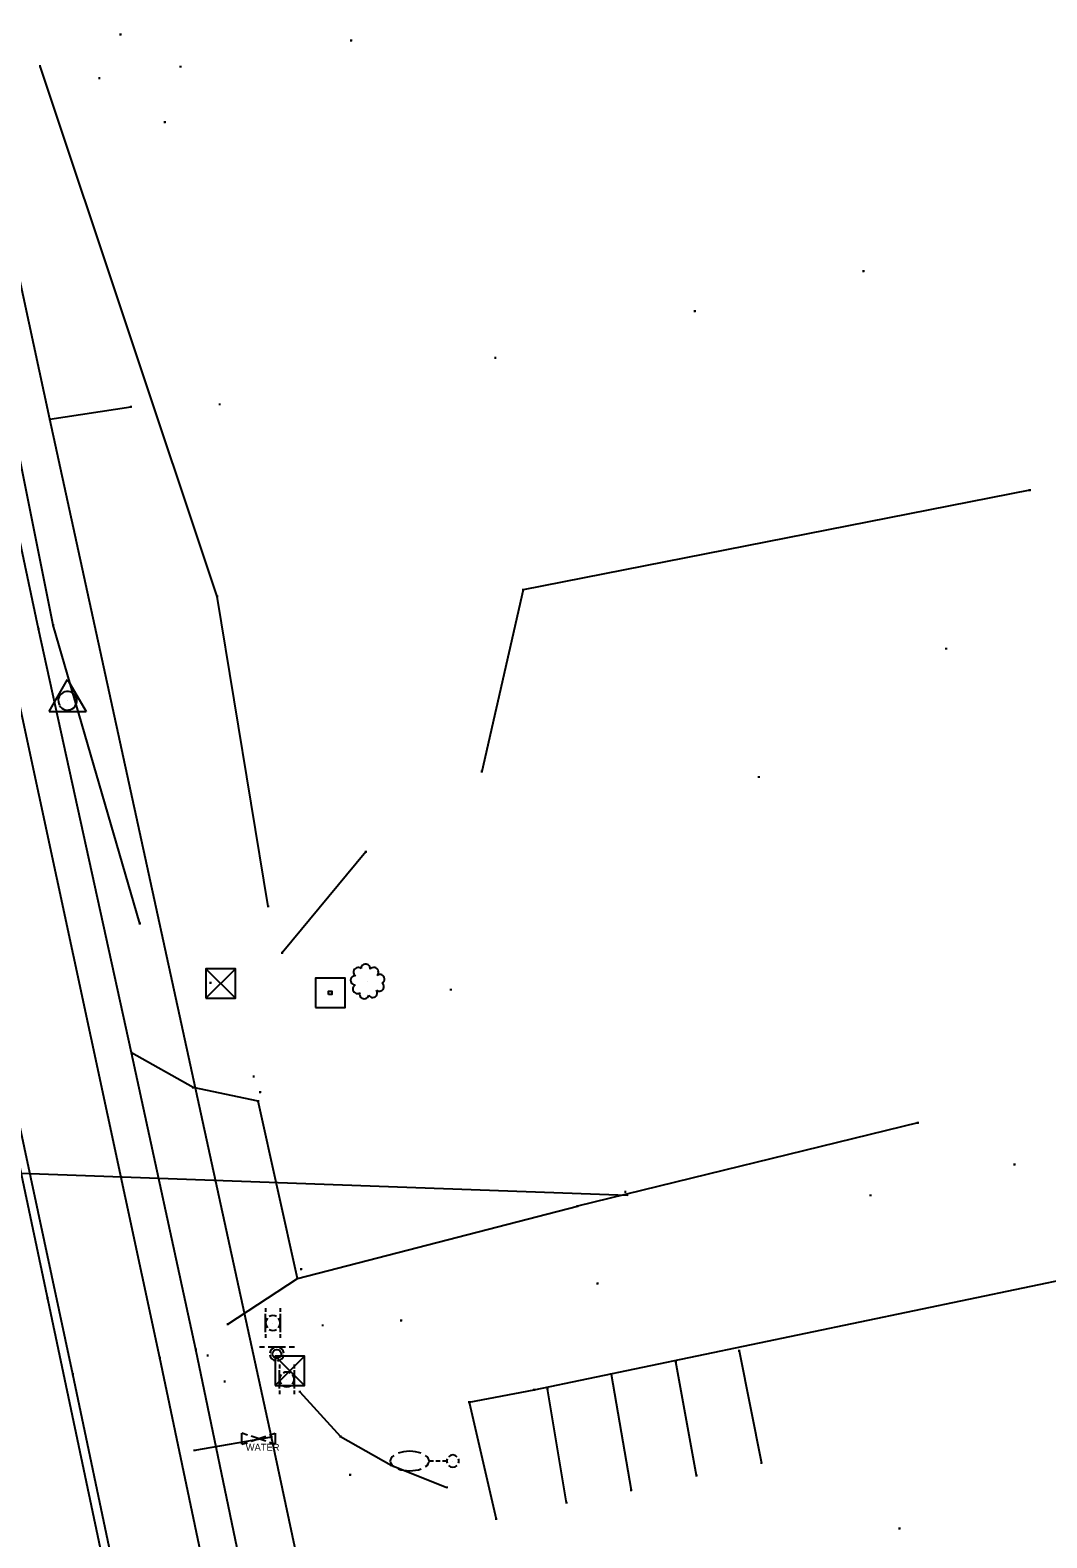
# Model space of a CAD drawing. Extents: x 1954856 to 2011933, y 399149 to 426294.
# Drawn here: x 2005902.3 to 2006040.2, y 403651.8 to 403856.4 of the extents above; entities that cross this region are included whole.
import ezdxf

# ---------------------------------------------------------------- set-up
doc = ezdxf.new("R2010")
doc.units = 0
for name, color, linetype in [('BankMent_ep', 7, 'Continuous'), ('BaselineSurvey', 7, 'Continuous'), ('DelineatorPost_ep', 7, 'Continuous'), ('Driveway_ep', 7, 'Continuous'), ('ElecAer_ep', 7, 'Continuous'), ('Fence_ep', 7, 'Continuous'), ('GroundShot_ep', 7, 'Continuous'), ('Luminaire_ep', 7, 'Continuous'), ('MonumentCC_ep', 7, 'Continuous'), ('MonumentIRC_ep', 7, 'Continuous'), ('MonumentPST_ep', 7, 'Continuous'), ('PavtAsphalt_ep', 7, 'Continuous'), ('PavtAsphaltCrown_ep', 7, 'Continuous'), ('PavtMisc_ep', 7, 'Continuous'), ('PMRK_ep', 7, 'Continuous'), ('PointLocator_ep', 7, 'Continuous'), ('ShldrPaved_ep', 7, 'Continuous'), ('SignSingle_ep', 7, 'Continuous'), ('TreeOak_ep', 7, 'Continuous'), ('ValveWater_ep', 7, 'Continuous'), ('WaterB_ep', 7, 'Continuous')]:
    doc.layers.add(name, color=color, linetype=linetype)

msp = doc.modelspace()

# ---------------------------------------------------------------- linework, layer by layer
at = {"layer": 'BankMent_ep'}
for p, q in [((2005927.68, 403779.55), (2005903.63, 403851.51)), ((2005905.4, 403775.65), (2005893.76, 403833.79)), ((2005917.19, 403735.17), (2005905.4, 403775.65)), ((2005947.84, 403744.92), (2005936.49, 403731.21))]:
    msp.add_line(p, q, dxfattribs=at)
msp.add_lwpolyline([(2005934.6, 403737.51), (2005927.68, 403779.55)], dxfattribs=at)
at = {"layer": 'BaselineSurvey'}
msp.add_line((2006223.92, 402174.38), (2005094.48, 407516.05), dxfattribs=at)
msp.add_line((2006223.92, 402174.38), (2005094.48, 407516.05), dxfattribs=at)
at = {"layer": 'DelineatorPost_ep'}
for p, q in [((2005934.23, 403682.97), (2005934.23, 403682.47)), ((2005934.23, 403679.72), (2005934.23, 403682.22)), ((2005936.23, 403682.97), (2005936.23, 403682.47)), ((2005936.23, 403682.22), (2005936.23, 403679.72)), ((2005934.23, 403679.47), (2005934.23, 403678.97)), ((2005935.23, 403680.97), (2005935.23, 403680.97)), ((2005936.23, 403679.47), (2005936.23, 403678.97)), ((2005936.12, 403675.32), (2005936.12, 403674.82)), ((2005938.12, 403675.32), (2005938.12, 403674.82)), ((2005936.12, 403672.07), (2005936.12, 403674.57)), ((2005937.12, 403673.32), (2005937.12, 403673.32)), ((2005938.12, 403674.57), (2005938.12, 403672.07)), ((2005936.12, 403671.82), (2005936.12, 403671.32)), ((2005938.12, 403671.82), (2005938.12, 403671.32))]:
    msp.add_line(p, q, dxfattribs=at)
for centre, start, end in [((2005935.23, 403680.97), 138.5904, 221.4096), ((2005935.23, 403680.97), 60, 120), ((2005935.23, 403680.97), 318.5904, 41.4096), ((2005935.23, 403680.97), 240, 300), ((2005937.12, 403673.32), 138.5904, 221.4096), ((2005937.12, 403673.32), 60, 120), ((2005937.12, 403673.32), 318.5904, 41.4096), ((2005937.12, 403673.32), 240, 300)]:
    msp.add_arc(centre, 1, start, end, dxfattribs=at)
at = {"layer": 'Driveway_ep'}
for p, q in [((2006037.93, 403793.98), (2005969.18, 403780.48)), ((2005969.18, 403780.48), (2005963.57, 403755.79)), ((2005924.4, 403712.93), (2005916.05, 403717.64)), ((2005933.24, 403711.08), (2005924.4, 403712.93)), ((2005938.57, 403687.03), (2005933.24, 403711.08)), ((2005929.13, 403680.81), (2005938.57, 403687.03)), ((2005961.87, 403670.23), (2005965.52, 403654.36))]:
    msp.add_line(p, q, dxfattribs=at)
for points in [[(2006037.93, 403793.98), (2005969.18, 403780.48), (2005963.57, 403755.79)], [(2006022.73, 403708.13), (2005976.55, 403696.84)], [(2005938.57, 403687.03), (2005976.55, 403696.84)]]:
    msp.add_lwpolyline(points, dxfattribs=at)
at = {"layer": 'ElecAer_ep'}
msp.add_lwpolyline([(2005962.93, 403244.33), (2005923.16, 403436.14), (2005867.36, 403702.52), (2005983.3, 403698.34)], dxfattribs=at)
at = {"layer": 'Fence_ep'}
msp.add_lwpolyline([(2005938.88, 403671.64), (2005944.41, 403665.56), (2005951.26, 403661.68), (2005958.83, 403658.67)], dxfattribs=at)
at = {"layer": 'GroundShot_ep'}
for p, q in [((2006015.49, 403823.71), (2006015.24, 403823.71)), ((2006015.36, 403823.58), (2006015.36, 403823.83)), ((2006015.36, 403823.71), (2006015.36, 403823.71)), ((2006026.71, 403772.47), (2006026.46, 403772.47)), ((2006026.58, 403772.35), (2006026.58, 403772.6)), ((2006026.58, 403772.47), (2006026.58, 403772.47)), ((2006035.98, 403702.49), (2006035.73, 403702.49)), ((2006035.85, 403702.36), (2006035.85, 403702.61)), ((2006035.85, 403702.49), (2006035.85, 403702.49))]:
    msp.add_line(p, q, dxfattribs=at)
at = {"layer": 'Luminaire_ep'}
for p, q in [((2005957.02, 403662.24), (2005956.42, 403662.24)), ((2005957.92, 403662.24), (2005957.32, 403662.24)), ((2005958.82, 403662.24), (2005958.22, 403662.24)), ((2005959.65, 403662.24), (2005959.65, 403662.24))]:
    msp.add_line(p, q, dxfattribs=at)
for start, end in [(45, 135), (159.9115, 200.0885), (225, 315), (339.9115, 20.0885)]:
    msp.add_arc((2005959.65, 403662.24), 0.825, start, end, dxfattribs=at)
for start_param, end_param in [(5.668326, 6.898045), (4.075781, 5.348997), (2.526733, 3.756452), (0.934187, 2.207405)]:
    msp.add_ellipse((2005953.78, 403662.24), major_axis=(-2.64, 0), ratio=0.5, start_param=start_param, end_param=end_param, dxfattribs=at)
at = {"layer": 'MonumentCC_ep'}
msp.add_line((2005943.01, 403725.78), (2005943.01, 403725.78), dxfattribs=at)
msp.add_lwpolyline([(2005941.01, 403723.78), (2005945.01, 403723.78), (2005945.01, 403727.78), (2005941.01, 403727.78), (2005941.01, 403723.78)], dxfattribs=at)
msp.add_lwpolyline([(2005942.77, 403725.55), (2005942.77, 403726.02), (2005943.24, 403726.02), (2005943.24, 403725.55)], close=True, dxfattribs=at)
at = {"layer": 'MonumentIRC_ep'}
for p, q in [((2005904.87, 403763.96), (2005907.37, 403768.29)), ((2005907.37, 403768.29), (2005909.87, 403763.96)), ((2005907.37, 403765.41), (2005907.37, 403765.41)), ((2005904.87, 403763.96), (2005909.87, 403763.96))]:
    msp.add_line(p, q, dxfattribs=at)
msp.add_arc((2005907.37, 403765.41), 1.26, 209.9294, 209.03, dxfattribs=at)
at = {"layer": 'MonumentPST_ep'}
for p, q in [((2005926.14, 403729.03), (2005930.14, 403725.03)), ((2005926.14, 403725.03), (2005930.14, 403729.03)), ((2005928.14, 403727.03), (2005928.14, 403727.03)), ((2005935.52, 403676.48), (2005939.52, 403672.48)), ((2005935.52, 403672.48), (2005939.52, 403676.48)), ((2005937.52, 403674.48), (2005937.52, 403674.48))]:
    msp.add_line(p, q, dxfattribs=at)
for points in [[(2005926.14, 403725.03), (2005930.14, 403725.03), (2005930.14, 403729.03), (2005926.14, 403729.03), (2005926.14, 403725.03)], [(2005935.52, 403672.48), (2005939.52, 403672.48), (2005939.52, 403676.48), (2005935.52, 403676.48), (2005935.52, 403672.48)]]:
    msp.add_lwpolyline(points, dxfattribs=at)
at = {"layer": 'PavtAsphalt_ep'}
msp.add_lwpolyline([(2006233.39, 402199.4), (2006231.31, 402208.78), (2006210.3, 402306.91), (2006189.73, 402404.41), (2006168.52, 402502.44), (2006147.45, 402600.55), (2006127, 402698.2), (2006106.48, 402795.48), (2006085.7, 402893.48), (2006064.78, 402991.32), (2006043.91, 403089.28), (2006023.05, 403187.5), (2006002.57, 403285.23), (2005981.7, 403382.7), (2005961.21, 403480.5), (2005940.45, 403578.3), (2005919.87, 403676.23), (2005898.84, 403774.26)], dxfattribs=at)
at = {"layer": 'PavtAsphaltCrown_ep'}
msp.add_lwpolyline([(2006221.58, 402197.04), (2006219.37, 402206.69), (2006198.42, 402304.43), (2006177.67, 402402.21), (2006156.49, 402500.14), (2006135.92, 402597.88), (2006115.39, 402695.49), (2006094.3, 402793.44), (2006073.8, 402891.43), (2006052.86, 402989.16), (2006032.08, 403086.96), (2006011.06, 403184.66), (2005990.58, 403282.63), (2005969.86, 403380.23), (2005949.3, 403478.33), (2005928.68, 403576.1), (2005908.1, 403674.03), (2005887.14, 403771.84)], dxfattribs=at)
at = {"layer": 'PavtMisc_ep'}
for points in [[(2005961.87, 403670.23), (2005970.68, 403671.89), (2006044.38, 403687.3), (2006113.91, 403701.04)], [(2005970.68, 403671.89), (2006044.38, 403687.3), (2006113.91, 403701.04)]]:
    msp.add_lwpolyline(points, dxfattribs=at)
at = {"layer": 'PMRK_ep'}
for points in [[(2005998.51, 403677.19), (2006001.5, 403661.97)], [(2005992.71, 403660.27), (2005989.91, 403675.69)], [(2005981.12, 403674.04), (2005983.83, 403658.27)], [(2005975.08, 403656.59), (2005972.5, 403672.03)]]:
    msp.add_lwpolyline(points, dxfattribs=at)
at = {"layer": 'PointLocator_ep'}
for p, q in [((2005914.67, 403855.81), (2005914.42, 403855.81)), ((2005914.54, 403855.69), (2005914.54, 403855.94)), ((2005914.54, 403855.81), (2005914.54, 403855.81)), ((2005945.96, 403854.99), (2005945.71, 403854.99)), ((2005945.83, 403854.86), (2005945.83, 403855.11)), ((2005945.83, 403854.99), (2005945.83, 403854.99)), ((2005903.75, 403851.51), (2005903.5, 403851.51)), ((2005903.63, 403851.38), (2005903.63, 403851.63)), ((2005903.63, 403851.51), (2005903.63, 403851.51)), ((2005922.82, 403851.45), (2005922.57, 403851.45)), ((2005922.69, 403851.33), (2005922.69, 403851.58)), ((2005922.69, 403851.45), (2005922.69, 403851.45)), ((2005911.8, 403849.9), (2005911.55, 403849.9)), ((2005911.68, 403849.77), (2005911.68, 403850.02)), ((2005911.68, 403849.9), (2005911.68, 403849.9)), ((2005920.7, 403843.91), (2005920.45, 403843.91)), ((2005920.58, 403843.78), (2005920.58, 403844.03)), ((2005920.58, 403843.91), (2005920.58, 403843.91)), ((2005992.49, 403818.13), (2005992.49, 403818.38)), ((2005992.61, 403818.26), (2005992.36, 403818.26)), ((2005992.49, 403818.26), (2005992.49, 403818.26)), ((2005965.53, 403811.92), (2005965.28, 403811.92)), ((2005965.41, 403811.79), (2005965.41, 403812.04)), ((2005965.41, 403811.92), (2005965.41, 403811.92)), ((2005916.09, 403805.27), (2005915.84, 403805.27)), ((2005915.96, 403805.15), (2005915.96, 403805.4)), ((2005915.96, 403805.27), (2005915.96, 403805.27)), ((2005928.14, 403805.63), (2005927.89, 403805.63)), ((2005928.01, 403805.5), (2005928.01, 403805.75)), ((2005928.01, 403805.63), (2005928.01, 403805.63)), ((2005905.1, 403803.61), (2005904.85, 403803.61)), ((2005904.97, 403803.49), (2005904.97, 403803.74)), ((2005904.97, 403803.61), (2005904.97, 403803.61)), ((2006038.06, 403793.98), (2006037.81, 403793.98)), ((2006037.93, 403793.86), (2006037.93, 403794.11)), ((2006037.93, 403793.98), (2006037.93, 403793.98)), ((2005927.8, 403779.55), (2005927.55, 403779.55)), ((2005927.68, 403779.43), (2005927.68, 403779.68)), ((2005927.68, 403779.55), (2005927.68, 403779.55)), ((2005969.31, 403780.48), (2005969.06, 403780.48)), ((2005969.18, 403780.36), (2005969.18, 403780.61)), ((2005969.18, 403780.48), (2005969.18, 403780.48)), ((2005905.53, 403775.65), (2005905.28, 403775.65)), ((2005905.4, 403775.53), (2005905.4, 403775.78)), ((2005905.4, 403775.65), (2005905.4, 403775.65)), ((2005903.54, 403775.17), (2005903.29, 403775.17)), ((2005903.42, 403775.04), (2005903.42, 403775.29)), ((2005903.42, 403775.17), (2005903.42, 403775.17)), ((2005963.7, 403755.79), (2005963.45, 403755.79)), ((2005963.57, 403755.67), (2005963.57, 403755.92)), ((2005963.57, 403755.79), (2005963.57, 403755.79)), ((2006001.28, 403755.05), (2006001.03, 403755.05)), ((2006001.16, 403754.93), (2006001.16, 403755.18)), ((2006001.16, 403755.05), (2006001.16, 403755.05)), ((2005947.97, 403744.92), (2005947.72, 403744.92)), ((2005947.84, 403744.79), (2005947.84, 403745.04)), ((2005947.84, 403744.92), (2005947.84, 403744.92)), ((2005934.72, 403737.51), (2005934.47, 403737.51)), ((2005934.6, 403737.39), (2005934.6, 403737.64)), ((2005934.6, 403737.51), (2005934.6, 403737.51)), ((2005917.31, 403735.17), (2005917.06, 403735.17)), ((2005917.19, 403735.04), (2005917.19, 403735.29)), ((2005917.19, 403735.17), (2005917.19, 403735.17)), ((2005936.61, 403731.21), (2005936.36, 403731.21)), ((2005936.49, 403731.08), (2005936.49, 403731.33)), ((2005936.49, 403731.21), (2005936.49, 403731.21)), ((2005926.88, 403727.12), (2005926.63, 403727.12)), ((2005926.75, 403726.99), (2005926.75, 403727.24)), ((2005926.75, 403727.12), (2005926.75, 403727.12)), ((2005959.36, 403726.07), (2005959.36, 403726.32)), ((2005959.49, 403726.2), (2005959.24, 403726.2)), ((2005959.36, 403726.2), (2005959.36, 403726.2)), ((2005916.18, 403717.64), (2005915.93, 403717.64)), ((2005916.05, 403717.52), (2005916.05, 403717.77)), ((2005916.05, 403717.64), (2005916.05, 403717.64)), ((2005932.75, 403714.42), (2005932.5, 403714.42)), ((2005932.63, 403714.3), (2005932.63, 403714.55)), ((2005932.63, 403714.42), (2005932.63, 403714.42)), ((2005924.53, 403712.93), (2005924.28, 403712.93)), ((2005924.4, 403712.8), (2005924.4, 403713.05)), ((2005924.4, 403712.93), (2005924.4, 403712.93)), ((2005933.62, 403712.29), (2005933.37, 403712.29)), ((2005933.5, 403712.16), (2005933.5, 403712.41)), ((2005933.5, 403712.29), (2005933.5, 403712.29)), ((2005933.37, 403711.08), (2005933.12, 403711.08)), ((2005933.24, 403710.95), (2005933.24, 403711.2)), ((2005933.24, 403711.08), (2005933.24, 403711.08)), ((2006022.85, 403708.13), (2006022.6, 403708.13)), ((2006022.73, 403708.01), (2006022.73, 403708.26)), ((2006022.73, 403708.13), (2006022.73, 403708.13)), ((2005983.17, 403698.77), (2005982.92, 403698.77)), ((2005983.05, 403698.64), (2005983.05, 403698.89)), ((2005983.05, 403698.77), (2005983.05, 403698.77)), ((2005983.43, 403698.34), (2005983.18, 403698.34)), ((2005983.3, 403698.21), (2005983.3, 403698.46)), ((2005983.3, 403698.34), (2005983.3, 403698.34)), ((2006016.43, 403698.29), (2006016.18, 403698.29)), ((2006016.31, 403698.17), (2006016.31, 403698.42)), ((2006016.31, 403698.29), (2006016.31, 403698.29)), ((2005976.68, 403696.84), (2005976.43, 403696.84)), ((2005976.55, 403696.71), (2005976.55, 403696.96)), ((2005976.55, 403696.84), (2005976.55, 403696.84)), ((2005939.2, 403688.27), (2005938.95, 403688.27)), ((2005939.08, 403688.15), (2005939.08, 403688.4)), ((2005939.08, 403688.27), (2005939.08, 403688.27)), ((2005938.69, 403687.03), (2005938.44, 403687.03)), ((2005938.57, 403686.91), (2005938.57, 403687.16)), ((2005938.57, 403687.03), (2005938.57, 403687.03)), ((2005979.42, 403686.31), (2005979.17, 403686.31)), ((2005979.29, 403686.18), (2005979.29, 403686.43)), ((2005979.29, 403686.31), (2005979.29, 403686.31)), ((2005904.78, 403684.34), (2005904.53, 403684.34)), ((2005904.78, 403684.34), (2005904.53, 403684.34)), ((2005904.65, 403684.21), (2005904.65, 403684.46)), ((2005904.65, 403684.21), (2005904.65, 403684.46)), ((2005904.65, 403684.34), (2005904.65, 403684.34)), ((2005904.65, 403684.34), (2005904.65, 403684.34)), ((2005952.76, 403681.29), (2005952.51, 403681.29)), ((2005952.63, 403681.17), (2005952.63, 403681.42)), ((2005952.63, 403681.29), (2005952.63, 403681.29)), ((2005929.25, 403680.81), (2005929, 403680.81)), ((2005929.13, 403680.68), (2005929.13, 403680.93)), ((2005929.13, 403680.81), (2005929.13, 403680.81)), ((2005942.11, 403680.65), (2005941.86, 403680.65)), ((2005941.99, 403680.52), (2005941.99, 403680.77)), ((2005941.99, 403680.65), (2005941.99, 403680.65)), ((2005924.92, 403677.39), (2005924.67, 403677.39)), ((2005924.79, 403677.26), (2005924.79, 403677.51)), ((2005924.79, 403677.39), (2005924.79, 403677.39)), ((2005998.63, 403677.19), (2005998.38, 403677.19)), ((2005998.51, 403677.07), (2005998.51, 403677.32)), ((2005998.51, 403677.19), (2005998.51, 403677.19)), ((2005920, 403676.23), (2005919.75, 403676.23)), ((2005919.87, 403676.11), (2005919.87, 403676.36)), ((2005919.87, 403676.23), (2005919.87, 403676.23)), ((2005926.5, 403676.55), (2005926.25, 403676.55)), ((2005926.38, 403676.42), (2005926.38, 403676.67)), ((2005926.38, 403676.55), (2005926.38, 403676.55)), ((2005990.03, 403675.69), (2005989.78, 403675.69)), ((2005989.91, 403675.56), (2005989.91, 403675.81)), ((2005989.91, 403675.69), (2005989.91, 403675.69)), ((2005908.23, 403674.03), (2005907.98, 403674.03)), ((2005908.1, 403673.9), (2005908.1, 403674.15)), ((2005908.1, 403674.03), (2005908.1, 403674.03)), ((2005928.69, 403672.9), (2005928.69, 403673.15)), ((2005981.24, 403674.04), (2005980.99, 403674.04)), ((2005981.12, 403673.92), (2005981.12, 403674.17)), ((2005981.12, 403674.04), (2005981.12, 403674.04)), ((2005928.81, 403673.02), (2005928.56, 403673.02)), ((2005928.69, 403673.02), (2005928.69, 403673.02)), ((2005939, 403671.64), (2005938.75, 403671.64)), ((2005938.88, 403671.52), (2005938.88, 403671.77)), ((2005938.88, 403671.64), (2005938.88, 403671.64)), ((2005970.8, 403671.89), (2005970.55, 403671.89)), ((2005970.68, 403671.76), (2005970.68, 403672.01)), ((2005970.68, 403671.89), (2005970.68, 403671.89)), ((2005972.63, 403672.03), (2005972.38, 403672.03)), ((2005972.5, 403671.9), (2005972.5, 403672.15)), ((2005972.5, 403672.03), (2005972.5, 403672.03)), ((2005962, 403670.23), (2005961.75, 403670.23)), ((2005961.87, 403670.1), (2005961.87, 403670.35)), ((2005961.87, 403670.23), (2005961.87, 403670.23)), ((2005935.19, 403665.48), (2005934.94, 403665.48)), ((2005935.06, 403665.36), (2005935.06, 403665.61)), ((2005935.06, 403665.48), (2005935.06, 403665.48)), ((2005944.53, 403665.56), (2005944.28, 403665.56)), ((2005944.41, 403665.43), (2005944.41, 403665.68)), ((2005944.41, 403665.56), (2005944.41, 403665.56)), ((2005924.74, 403663.68), (2005924.49, 403663.68)), ((2005924.61, 403663.56), (2005924.61, 403663.81)), ((2005924.61, 403663.68), (2005924.61, 403663.68)), ((2005951.39, 403661.68), (2005951.14, 403661.68)), ((2005951.26, 403661.55), (2005951.26, 403661.8)), ((2005951.26, 403661.68), (2005951.26, 403661.68)), ((2006001.62, 403661.97), (2006001.37, 403661.97)), ((2006001.5, 403661.84), (2006001.5, 403662.09)), ((2006001.5, 403661.97), (2006001.5, 403661.97)), ((2005945.83, 403660.37), (2005945.58, 403660.37)), ((2005945.71, 403660.24), (2005945.71, 403660.49)), ((2005945.71, 403660.37), (2005945.71, 403660.37)), ((2005958.83, 403658.55), (2005958.83, 403658.8)), ((2005992.84, 403660.27), (2005992.59, 403660.27)), ((2005992.71, 403660.14), (2005992.71, 403660.39)), ((2005992.71, 403660.27), (2005992.71, 403660.27)), ((2005958.96, 403658.67), (2005958.71, 403658.67)), ((2005958.83, 403658.67), (2005958.83, 403658.67)), ((2005975.08, 403656.47), (2005975.08, 403656.72)), ((2005983.95, 403658.27), (2005983.7, 403658.27)), ((2005983.83, 403658.14), (2005983.83, 403658.39)), ((2005983.83, 403658.27), (2005983.83, 403658.27)), ((2005975.2, 403656.59), (2005974.95, 403656.59)), ((2005975.08, 403656.59), (2005975.08, 403656.59)), ((2005965.64, 403654.36), (2005965.39, 403654.36)), ((2005965.52, 403654.24), (2005965.52, 403654.49)), ((2005965.52, 403654.36), (2005965.52, 403654.36)), ((2006020.39, 403653.09), (2006020.14, 403653.09)), ((2006020.26, 403652.96), (2006020.26, 403653.21)), ((2006020.26, 403653.09), (2006020.26, 403653.09))]:
    msp.add_line(p, q, dxfattribs=at)
at = {"layer": 'ShldrPaved_ep'}
for points in [[(2005903.42, 403775.17), (2005882.61, 403873.3), (2005862.4, 403970.53), (2005841.95, 404068.79), (2005833.02, 404111.96), (2005824.07, 404153.86), (2005821.13, 404166.76), (2005800.41, 404264.66), (2005790.98, 404309.78), (2005786.66, 404328.77), (2005780.09, 404362.8), (2005777.01, 404374.53), (2005775.45, 404382.87), (2005759.1, 404460.96), (2005738.67, 404557.71), (2005723.06, 404628.5), (2005720.92, 404639.79), (2005717.5, 404656.37), (2005696.64, 404753.71), (2005676.04, 404851.63), (2005665.59, 404900.23), (2005661.01, 404921.05)], [(2006236.97, 402200.29), (2006234.96, 402209.44), (2006223.13, 402265.91), (2006222.91, 402271.95), (2006207.49, 402343.57), (2006194.34, 402405.59), (2006173.46, 402503.37), (2006152.82, 402601.72), (2006132.25, 402699.3), (2006111.09, 402796.88), (2006090.39, 402894.56), (2006069.53, 402992.45), (2006048.7, 403090.06), (2006039.79, 403131.91), (2006031.78, 403169.97), (2006021.65, 403217.64), (2006000.24, 403320.06), (2005986.36, 403383.8), (2005966.07, 403481.27), (2005945.25, 403579.6), (2005942.29, 403592.9), (2005924.79, 403677.39), (2005916.05, 403717.64), (2005903.42, 403775.17)]]:
    msp.add_lwpolyline(points, dxfattribs=at)
at = {"layer": 'SignSingle_ep'}
for p, q in [((2005933.39, 403677.72), (2005934.09, 403677.72)), ((2005934.59, 403677.72), (2005936.94, 403677.72)), ((2005937.44, 403677.72), (2005938.14, 403677.72)), ((2005935.77, 403676.77), (2005935.77, 403676.77))]:
    msp.add_line(p, q, dxfattribs=at)
msp.add_circle((2005935.77, 403676.77), 0.594, dxfattribs=at)
for start, end in [(96.0423, 173.9577), (6.0423, 83.9577), (186.0423, 263.9577), (276.0423, 353.9577)]:
    msp.add_arc((2005935.77, 403676.77), 0.95, start, end, dxfattribs=at)
at = {"layer": 'TreeOak_ep'}
msp.add_line((2005948.03, 403727.32), (2005948.03, 403727.32), dxfattribs=at)
for centre, radius, start, end in [((2005946.8, 403728.59), 0.624, 50.7185, 233.084), ((2005947.82, 403729.04), 0.629, 355.3943, 176.6549), ((2005948.93, 403728.59), 0.627, 315.0898, 140.6833), ((2005946.39, 403727.47), 0.625, 87.3095, 269.5618), ((2005946.69, 403726.3), 0.626, 119.4469, 301.0197), ((2005949.67, 403726.62), 0.623, 229.2872, 51.2025), ((2005949.75, 403727.65), 0.626, 299.4354, 127.2613), ((2005947.62, 403725.59), 0.625, 164.2871, 346.2767), ((2005948.76, 403725.77), 0.628, 211.1877, 36.8199)]:
    msp.add_arc(centre, radius, start, end, dxfattribs=at)
at = {"layer": 'ValveWater_ep'}
for p, q in [((2005931.78, 403665.77), (2005931.03, 403666.02)), ((2005931.03, 403664.52), (2005931.03, 403666.02)), ((2005934.28, 403664.94), (2005932.28, 403665.6)), ((2005932.28, 403664.94), (2005934.28, 403665.6)), ((2005933.28, 403665.27), (2005933.28, 403665.27)), ((2005934.78, 403665.77), (2005935.53, 403666.02)), ((2005935.53, 403666.02), (2005935.53, 403664.52)), ((2005931.03, 403664.52), (2005931.78, 403664.77)), ((2005935.53, 403664.52), (2005934.78, 403664.77))]:
    msp.add_line(p, q, dxfattribs=at)
at = {"layer": 'WaterB_ep'}
for points in [[(2005904.97, 403803.61), (2005872.12, 403956), (2005839.6, 404105.98), (2005853.73, 404109.45)], [(2005935.06, 403665.48), (2005904.97, 403803.61), (2005915.96, 403805.27)], [(2005935.06, 403665.48), (2005904.97, 403803.61), (2005915.96, 403805.27)], [(2005947.59, 403606.4), (2005935.06, 403665.48), (2005924.61, 403663.68)], [(2005947.59, 403606.4), (2005935.06, 403665.48), (2005924.61, 403663.68)]]:
    msp.add_lwpolyline(points, dxfattribs=at)

# ---------------------------------------------------------------- texts
at = {"layer": 'ValveWater_ep'}
msp.add_text('WATER', height=0.95, dxfattribs=at).set_placement((2005931.54, 403663.63))

doc.saveas('drawing.dxf')
